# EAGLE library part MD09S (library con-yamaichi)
YAMAICHI CONNECTOR
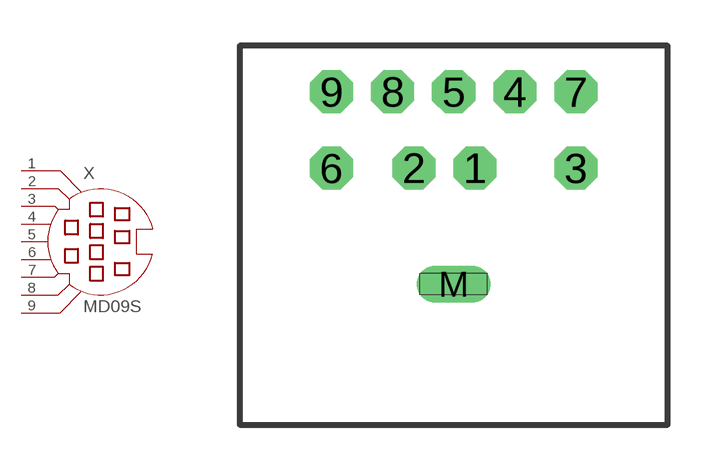
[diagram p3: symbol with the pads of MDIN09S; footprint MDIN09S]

Designator prefix X

## MD09S (OC_FARNELL: unknown; OC_NEWARK: unknown)  [MDIN09S]
1  1  pas
2  2  pas
3  3  pas
4  4  pas
5  5  pas
6  6  pas
7  7  pas
8  8  pas
9  9  pas

## Footprint MDIN09S (pad centres in mm)
Mini Din YAMAICHI CONNECTOR
drill 0.9 octagon: 1 0.7,8.5; 2 -1.3,8.5; 3 4,8.5; 4 2,11; 5 0,11; 6 -4,8.5; 7 4,11; 8 -2,11; 9 -4,11
drill 0.7 long: M 0,4.7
